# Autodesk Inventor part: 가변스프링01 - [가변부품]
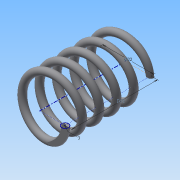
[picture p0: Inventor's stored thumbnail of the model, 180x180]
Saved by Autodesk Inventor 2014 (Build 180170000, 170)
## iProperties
Created: 2015-09
Part Number: 가변스프링01 - [가변부품]
Material: 강철, 탄소
Document SubType Name: Modeling
Designer: study
Density: 7.87 g/cm^3
Appearance: 반연마
Mass: 18.6318 g
Surface Area: 32.4192 cm^2
Volume: 2.36745 cm^3
Author: study
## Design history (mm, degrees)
sketch "스케치1"
  geometry: L1 (0, 0)-(11, 0); L2 (11, 0)-(11, 25.358); L3 (11, 25.358)-(0, 25.358); L4 (0, 25.358)-(0, 0); C1 r 1.5 at (11, 0)
  constraints: 8 end point, 2 parallel, 1 centre point, 1 coincident, 1 horizontal, 1 perpendicular
  dimensions: "d0" = 3 diameter of C1; "d1" = 22 diameter of L2 L4; "d2" = 25.35829 distance of L1.end L2.end (derived)
feature "코일1" pitch "d3" = 10; turns "d5" = 5; dims "d4" = 25.35829 (= d2), "d6" = 0, angle "d7" = 90 deg, angle "d8" = 90 deg, "d9" = 0, "d10" = 0
node "작업 평면1"
sketch "스케치2"
  geometry: L1 (-12.5, 0)-(-9.5, 0) reference; L2 (-12.5, 0)-(-9.5, 0) reference; 1 further point
  constraints: 2 horizontal alignment
extrude "돌출1" cut sketch "스케치2" stored distance "d12" = 10; taper "d13" = 0 deg
node "작업 평면2"
sketch "스케치3"
  geometry: L1 (-9.5, 0)-(-12.5, 0) reference; 1 further point
  constraints: 1 horizontal alignment
extrude "돌출2" cut sketch "스케치3" stored distance "d15" = 10; taper "d16" = 0 deg
node "솔리드1"
node "절단 모서리 투영1"
node "절단 모서리 투영2"
node "절단 모서리 투영3"
other parameters: "d11" = 0, "d14" = 25.35829 (= d2)
